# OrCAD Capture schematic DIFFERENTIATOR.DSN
size A
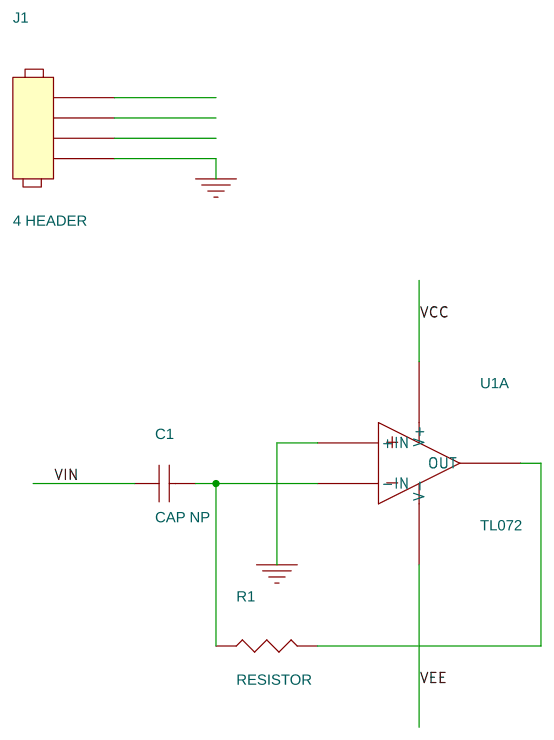
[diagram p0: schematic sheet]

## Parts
C1  CAP NP  [0402-CAP]
J1  4 HEADER  [JUMPER4]
R1  RESISTOR  [0402-RES]
U1  TL072  (section A)

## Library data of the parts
C1 = CAP_NP
J1 = 4_HEADER
R1 = RESISTOR
U1 = TL072

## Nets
GND: J1.4 U1.3(+IN)
VCC: U1.8(V+)
VEE: U1.4(V-)
VIN: C1.1
N00191: C1.2 R1.1 U1.2(-IN)
N00241: R1.2 U1.1(OUT)

Not connected (* = marked no-connect by the designer): J1 1 2 3
